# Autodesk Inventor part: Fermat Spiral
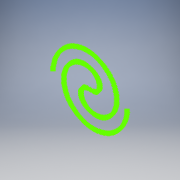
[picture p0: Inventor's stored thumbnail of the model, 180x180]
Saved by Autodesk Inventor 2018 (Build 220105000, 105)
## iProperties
Created: 2008-02
Part Number: Fermat Spiral
Document SubType Name: Modeling
Designer: Autodesk, Inc.
Density: 1 g/cm^3
Material: Generic
Appearance: Default
Author: Autodesk, Inc.
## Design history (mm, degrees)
sketch "Sketch1"
  geometry: 301 further points
  constraints: 301 other
